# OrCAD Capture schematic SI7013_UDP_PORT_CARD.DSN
size B; title: Si7013 UDP port card; rev: 1.0
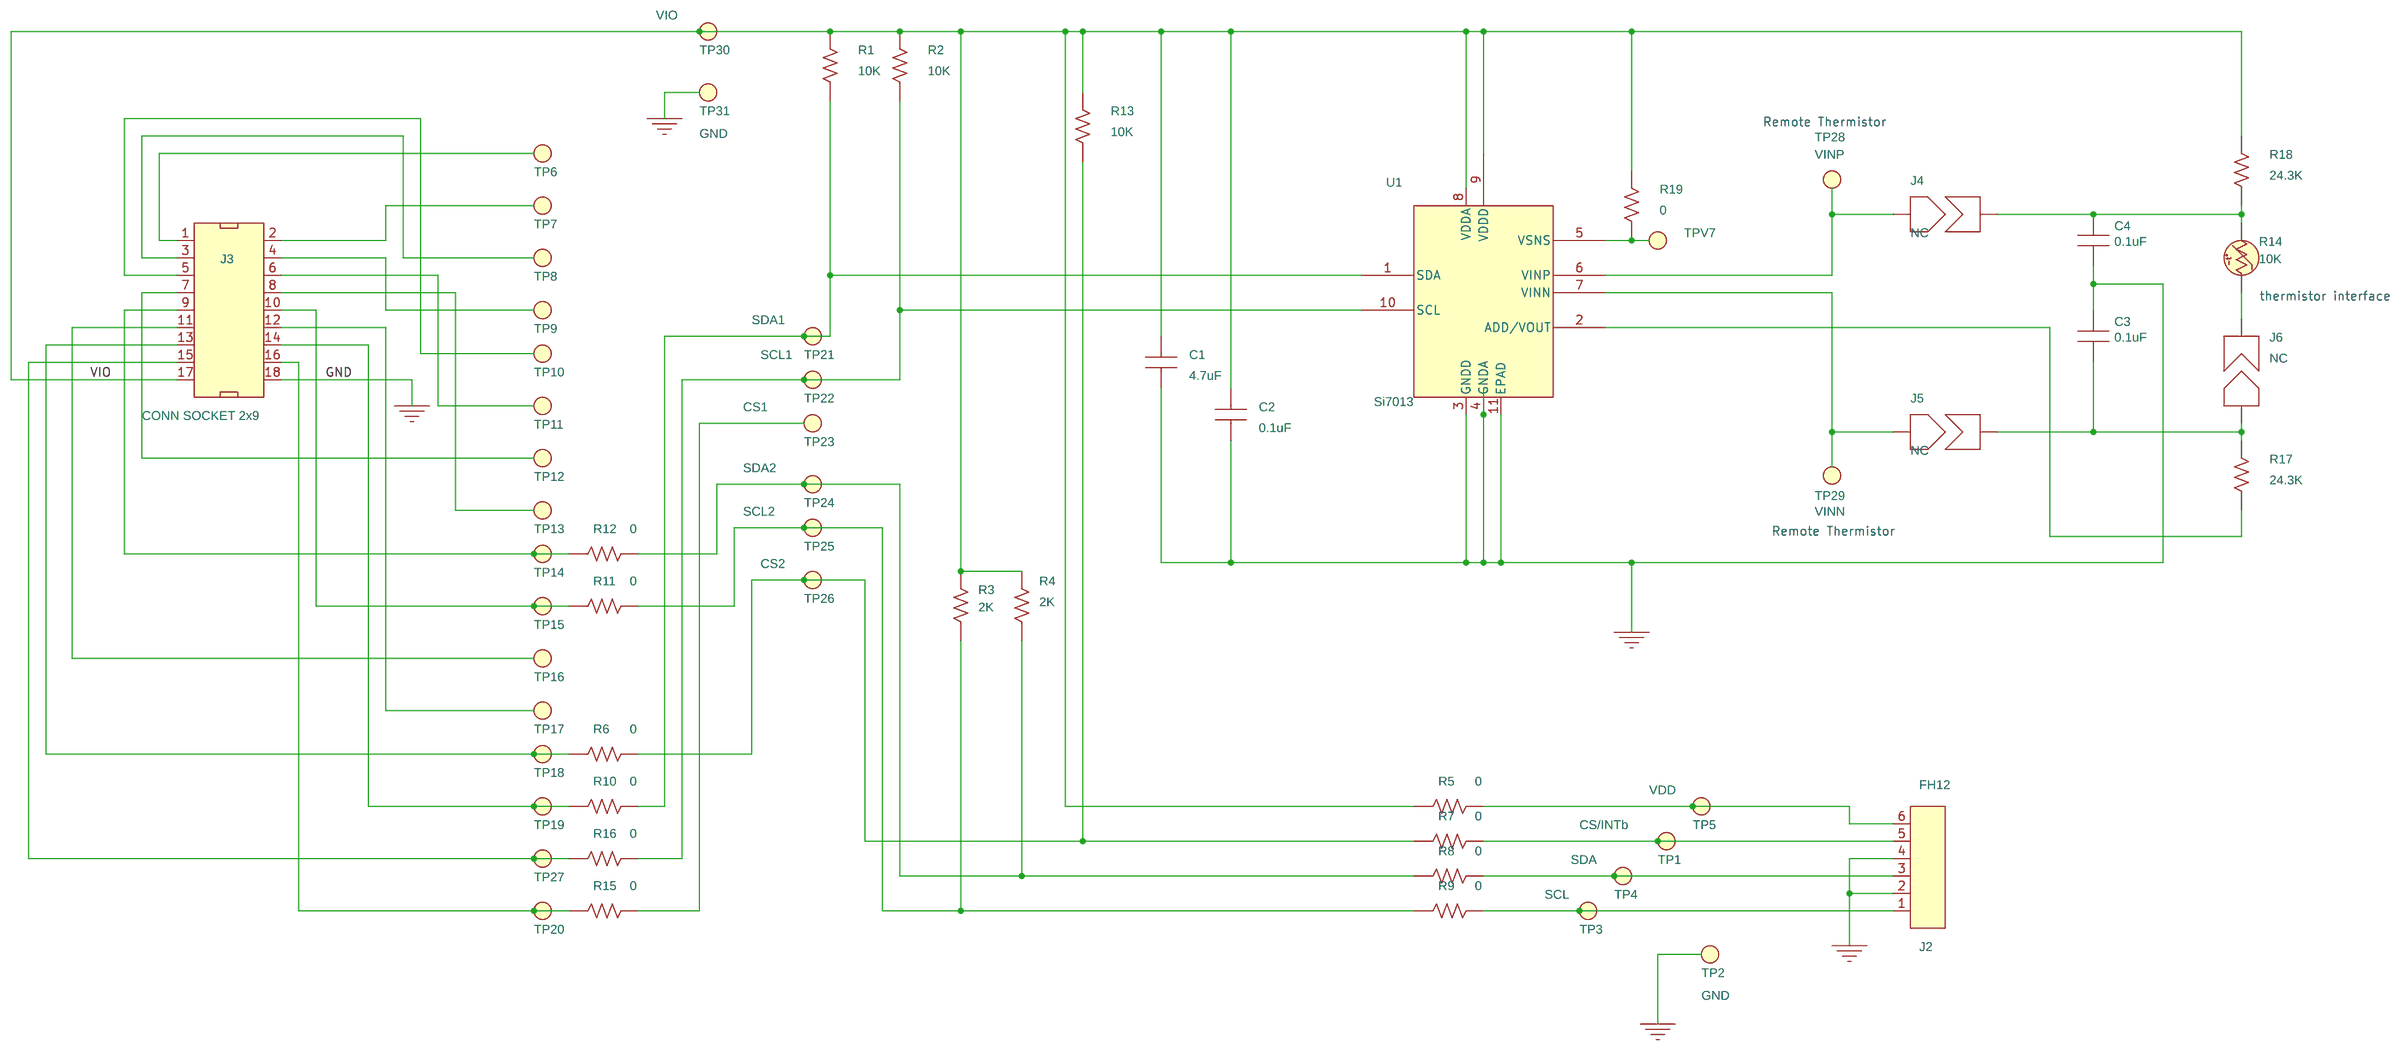
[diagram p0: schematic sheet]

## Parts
C1  4.7uF  [C0603]
C2  0.1uF  [C0402]
C3  0.1uF  [C0402]
C4  0.1uF  [C0402]
J2  FH12  [CONN6N-FPC/FFC-P0.5]
J3  CONN SOCKET 2x9  [CONN2X9-SKT-RA]
J4  NC  [SB0402-NC]
J5  NC  [SB0402-NC]
J6  NC  [SB0402-NC]
R1  10K  [R0402]
R2  10K  [R0402]
R3  2K  [R0402]
R4  2K  [R0402]
R5  0  [R0402]
R6  0  [R0402]
R7  0  [R0402]
R8  0  [R0402]
R9  0  [R0402]
R10  0  [R0402]
R11  0  [R0402]
R12  0  [R0402]
R13  10K  [R0402]
R14  10K  [R0603]
R15  0  [R0402]
R16  0  [R0402]
R17  24.3K  [R0603]
R18  24.3K  [R0603]
R19  0  [R0402]
TP1  TPV  [VIA-TP]
TP2  TPV  [VIA-TP]
TP3  TPV  [VIA-TP]
TP4  TPV  [VIA-TP]
TP5  TPV  [VIA-TP]
TP6  TPV  [VIA-TP]
TP7  TPV  [VIA-TP]
TP8  TPV  [VIA-TP]
TP9  TPV  [VIA-TP]
TP10  TPV  [VIA-TP]
TP11  TPV  [VIA-TP]
TP12  TPV  [VIA-TP]
TP13  TPV  [VIA-TP]
TP14  TPV  [VIA-TP]
TP15  TPV  [VIA-TP]
TP16  TPV  [VIA-TP]
TP17  TPV  [VIA-TP]
TP18  TPV  [VIA-TP]
TP19  TPV  [VIA-TP]
TP20  TPV  [VIA-TP]
TP21  TPV  [VIA-TP]
TP22  TPV  [VIA-TP]
TP23  TPV  [VIA-TP]
TP24  TPV  [VIA-TP]
TP25  TPV  [VIA-TP]
TP26  TPV  [VIA-TP]
TP27  TPV  [VIA-TP]
TP28  BLACK  [TESTPOINT]
TP29  BLACK  [TESTPOINT]
TP30  TPV  [VIA-TP]
TP31  TPV  [VIA-TP]
TPV7  TPV  [VIA-TP]
U1  Si7013  [DFN10M3X3P0.5E1.4X2.6]

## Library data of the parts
C1 = CAP_NP: CAP, 4.7uF, 6.3V, ±10%, X5R, 0603; Manufacturer: Venkel; ManufacturerPN: C0603X5R6R3-475K; Part_Type: CAP/NP; SiLabsPN: C0603X5R6R3-475K; Tolerance: ±10%; Type: X5R; Voltage: 6.3V; Datasheet: PID_C.pdf
C2 = CAP_NP: CAP, 0.1uF, 10V, ±10%, X7R, 0402; Manufacturer: Venkel; ManufacturerPN: C0402X7R100-104K; Part_Type: CAP/NP; SiLabsPN: C0402X7R100-104K; Tolerance: ±10%; Type: X7R; Voltage: 10V; Datasheet: PID_C.pdf
C3 C4 = CAP_NP: CAP, 0.1uF, 10V, ±20%, X7R, 0402; Manufacturer: Venkel; ManufacturerPN: C0402X7R100-104M; SiLabsPN: C0402X7R100-104M; Tolerance: ±20%; Type: X7R; Voltage: 10V; Datasheet: PID_C.pdf
J2 = CON6: CONN, 6-PIN , FPC/FFC, BOTTOM CONTACT, 0.5MM PITCH, SMD; Manufacturer: HIROSE; ManufacturerPN: FH12-6S-0.5SH(55); Part_Type: CON/MODULAR; SiLabsPN: FH12-6S-0.5SH(55); Datasheet: e58605370.pdf
J3 = CONN_2x9: CONN, Socket, 2x9, 0.1in pitch, Right angle, Flash Au Plated; Manufacturer: Samtec; ManufacturerPN: SSW-109-02-F-D-RA; SiLabsPN: SSW-109-02-F-D-RA; Type: Socket; Datasheet: SSW_TH.pdf
J4-J6 = SolderBump: SOLDER BUMP JUMPER, NC, 0402; Manufacturer: N/A; ManufacturerPN: N/A; Type: PCB Feature
R1 R2 R13 = RES: RES, 10K, 1/16W, ±1%, ThickFilm, 0402; Manufacturer: Venkel; ManufacturerPN: CR0402-16W-1002F; Rating: 1/16W; SiLabsPN: CR0402-16W-1002F; Tolerance: ±1%; Type: ThickFilm; Datasheet: PID_CR.pdf
R3 R4 = RES: RES, 2K, 1/16W, ±1%, ThickFilm, 0402; Manufacturer: Venkel; ManufacturerPN: CR0402-16W-2001F; Rating: 1/16W; SiLabsPN: CR0402-16W-2001F; Tolerance: ±1%; Type: ThickFilm; Datasheet: PID_CR.pdf
R5-R12 R15 R16 R19 = RES: RES, 0 Ohm, 1A, ThickFilm, 0402; Manufacturer: Venkel; ManufacturerPN: CR0402-16W-000; Rating: 1A; SiLabsPN: CR0402-16W-000; Type: ThickFilm; Datasheet: PID_CR.pdf
R14 = Thermistor: Thermistor, 10K, ±1%, 0603; Manufacturer: Murata; ManufacturerPN: NCP18XH103F03RB; SiLabsPN: NCP18XH103F03RB; Tolerance: ±1%; Type: NTC; Datasheet: r44e.pdf
R17 R18 = RES: RES, 24.3K, 1/16W, ±1%, ThickFilm, 0603; Manufacturer: Venkel; ManufacturerPN: CR0603-16W-2432F; Rating: 1/16W; SiLabsPN: CR0603-16W-2432F; Tolerance: ±1%; Type: ThickFilm; Datasheet: PID_CR.pdf
TP1 = TPV: TESTPOINT Via; Manufacturer: N/A; ManufacturerPN: N/A; Silk: CS/INTb; Type: PCB Feature
TP2 TP31 = TPV: TESTPOINT Via; Manufacturer: N/A; ManufacturerPN: N/A; Silk: GND; Type: PCB Feature
TP3 = TPV: TESTPOINT Via; Manufacturer: N/A; ManufacturerPN: N/A; Silk: SCL; Type: PCB Feature
TP4 = TPV: TESTPOINT Via; Manufacturer: N/A; ManufacturerPN: N/A; Silk: SDA; Type: PCB Feature
TP5 = TPV: TESTPOINT Via; Manufacturer: N/A; ManufacturerPN: N/A; Silk: VDD; Type: PCB Feature
TP6 = TPV: TESTPOINT Via; Manufacturer: N/A; ManufacturerPN: N/A; Silk: 0.0; Type: PCB Feature
TP7 = TPV: TESTPOINT Via; Manufacturer: N/A; ManufacturerPN: N/A; Silk: 0.1; Type: PCB Feature
TP8 = TPV: TESTPOINT Via; Manufacturer: N/A; ManufacturerPN: N/A; Silk: 0.2; Type: PCB Feature
TP9 = TPV: TESTPOINT Via; Manufacturer: N/A; ManufacturerPN: N/A; Silk: 0.3; Type: PCB Feature
TP10 = TPV: TESTPOINT Via; Manufacturer: N/A; ManufacturerPN: N/A; Silk: 0.4; Type: PCB Feature
TP11 = TPV: TESTPOINT Via; Manufacturer: N/A; ManufacturerPN: N/A; Silk: 0.5; Type: PCB Feature
TP12 = TPV: TESTPOINT Via; Manufacturer: N/A; ManufacturerPN: N/A; Silk: 0.6; Type: PCB Feature
TP13 = TPV: TESTPOINT Via; Manufacturer: N/A; ManufacturerPN: N/A; Silk: 0.7; Type: PCB Feature
TP14 = TPV: TESTPOINT Via; Manufacturer: N/A; ManufacturerPN: N/A; Silk: 1.0; Type: PCB Feature
TP15 = TPV: TESTPOINT Via; Manufacturer: N/A; ManufacturerPN: N/A; Silk: 1.1; Type: PCB Feature
TP16 = TPV: TESTPOINT Via; Manufacturer: N/A; ManufacturerPN: N/A; Silk: 1.2; Type: PCB Feature
TP17 = TPV: TESTPOINT Via; Manufacturer: N/A; ManufacturerPN: N/A; Silk: 1.3; Type: PCB Feature
TP18 = TPV: TESTPOINT Via; Manufacturer: N/A; ManufacturerPN: N/A; Silk: 1.4; Type: PCB Feature
TP19 = TPV: TESTPOINT Via; Manufacturer: N/A; ManufacturerPN: N/A; Silk: 1.5; Type: PCB Feature
TP20 = TPV: TESTPOINT Via; Manufacturer: N/A; ManufacturerPN: N/A; Silk: 1.7; Type: PCB Feature
TP21 = TPV: TESTPOINT Via; Manufacturer: N/A; ManufacturerPN: N/A; Silk: SDA1; Type: PCB Feature
TP22 = TPV: TESTPOINT Via; Manufacturer: N/A; ManufacturerPN: N/A; Silk: SCL1; Type: PCB Feature
TP23 = TPV: TESTPOINT Via; Manufacturer: N/A; ManufacturerPN: N/A; Silk: CS1; Type: PCB Feature
TP24 = TPV: TESTPOINT Via; Manufacturer: N/A; ManufacturerPN: N/A; Silk: SDA2; Type: PCB Feature
TP25 = TPV: TESTPOINT Via; Manufacturer: N/A; ManufacturerPN: N/A; Silk: SCL2; Type: PCB Feature
TP26 = TPV: TESTPOINT Via; Manufacturer: N/A; ManufacturerPN: N/A; Silk: CS2; Type: PCB Feature
TP27 = TPV: TESTPOINT Via; Manufacturer: N/A; ManufacturerPN: N/A; Silk: 1.6; Type: PCB Feature
TP28 = TEST_POINT: TESTPOINT, BLACK, PTH; Manufacturer: Kobiconn; ManufacturerPN: 151-203-RC; SiLabsPN: 151-203; Silk: VINP; Type: Loop; Datasheet: KC-300780.pdf
TP29 = TEST_POINT: TESTPOINT, BLACK, PTH; Manufacturer: Kobiconn; ManufacturerPN: 151-203-RC; SiLabsPN: 151-203; Silk: VINN; Type: Loop; Datasheet: KC-300780.pdf
TP30 = TPV: TESTPOINT Via; Manufacturer: N/A; ManufacturerPN: N/A; Silk: VIO; Type: PCB Feature
TPV7 = TPV: TESTPOINT Via; Manufacturer: N/A; ManufacturerPN: N/A; Type: PCB Feature
U1 = Si7013: IC, SENSOR, HUMIDITY, DFN10; Manufacturer: SiLabs; ManufacturerPN: Si7013-A-GM; SiLabsPN: Si7013-A-GM; Type: Sensor; Voltage: +4.2V; Datasheet: Si7013 Rev 0 2 draft 3 5 2013.pdf

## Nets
GND: C1.1 C2.1 C3.1 C4.2 J2.2 J2.4 J3.18 TP2.1(Point) TP31.1(Point) U1.3(GNDD) U1.4(GNDA) U1.11(EPAD)
VIO: C1.2 C2.2 J3.17 R1.2 R2.2 R3.2 R4.2 R5.1 R13.2 R18.2 R19.2 TP30.1(Point) U1.8(VDDA) U1.9(VDDD)
N16530649: J2.5 R7.2 TP1.1(Point)
N16656669: J2.1 R9.2 TP3.1(Point)
N16670007: J2.3 R8.2 TP4.1(Point)
N16779706: J2.6 R5.2 TP5.1(Point)
N16783241: R3.1 R9.1 R11.2 TP25.1(Point)
N16783283: R4.1 R8.1 R12.2 TP24.1(Point)
N16783307: R6.2 R7.1 R13.1 TP26.1(Point)
N16794213: R1.1 R10.2 TP21.1(Point) U1.1(SDA)
N16797556: J3.1 TP6.1(Point)
N16797753: J3.2 TP7.1(Point)
N16797769: J3.3 TP8.1(Point)
N16797789: J3.4 TP9.1(Point)
N16797803: J3.5 TP10.1(Point)
N16797823: J3.6 TP11.1(Point)
N16797832: J3.7 TP12.1(Point)
N16797853: J3.8 TP13.1(Point)
N16797872: J3.9 R12.1 TP14.1(Point)
N16797906: J3.10 R11.1 TP15.1(Point)
N16797950: J3.11 TP16.1(Point)
N16797959: J3.12 TP17.1(Point)
N16797971: J3.13 R6.1 TP18.1(Point)
N16797980: J3.14 R10.1 TP19.1(Point)
N16798002: J3.15 R16.1 TP27.1(Point)
N16798018: J3.16 R15.1 TP20.1(Point)
N16798340: R2.1 R16.2 TP22.1(Point) U1.10(SCL)
N16799371: R15.2 TP23.1(Point)
N16803883: C4.1 J4.2(IO2) R14.2 R18.1
N16803885: C3.2 J5.2(IO2) J6.1(IO1) R17.2
N16803908: J6.2(IO2) R14.1
N16803918: R17.1 U1.2(ADD/VOUT)
N16803930: R19.1 TPV7.1(Point) U1.5(VSNS)
N16804033: J4.1(IO1) TP28.1(Point) U1.6(VINP)
N16804041: J5.1(IO1) TP29.1(Point) U1.7(VINN)

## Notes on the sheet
- Remote Thermistor
- thermistor interface
- Remote Thermistor
